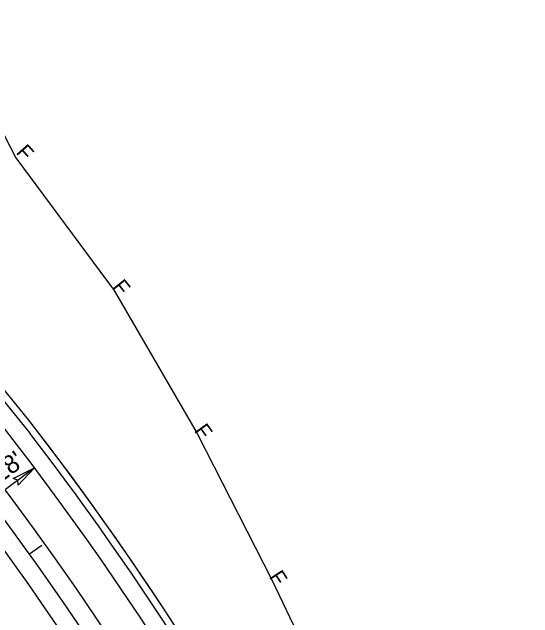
# Model space of a CAD drawing. Extents: x 1702862 to 1704514, y 793768 to 796215.
# Drawn here: x 1703795.7 to 1703965.8, y 794687 to 794884.7 of the extents above; entities that cross this region are included whole.
import ezdxf

# ---------------------------------------------------------------- set-up
doc = ezdxf.new("R2010")
doc.units = 0
for name, color, linetype in [('Prop Conc 2ft 6in Curb and Gutter', 7, 'Continuous'), ('Prop Conc Shoulder Berm Gutter', 7, 'Continuous'), ('Prop Dimension', 7, 'Continuous'), ('Prop Dimension Text', 7, 'Continuous'), ('Prop EOT', 7, 'Continuous'), ('Prop Guardrail', 7, 'Continuous'), ('Prop Horizontal Alignment', 7, 'Continuous'), ('Prop Horizontal Alignment Tick Small', 7, 'Continuous'), ('Prop Lane Lines', 7, 'Continuous'), ('Prop Paved Shoulder', 7, 'Continuous'), ('Prop SS Fill Line', 7, 'Continuous'), ('Prop SS Misc', 7, 'Continuous'), ('Prop Terminator CELL', 7, 'Continuous')]:
    doc.layers.add(name, color=color, linetype=linetype)

msp = doc.modelspace()

# ---------------------------------------------------------------- linework, layer by layer
at = {"layer": 'Prop Conc 2ft 6in Curb and Gutter'}
msp.add_arc((1702985.28, 794122.36), 970.46, 32.25438, 42.65517, dxfattribs=at)
at = {"layer": 'Prop Conc Shoulder Berm Gutter'}
for centre, radius, start, end in [((1703001.88, 794109.24), 1025.44, 38.5857, 43.82566), ((1702988.97, 794124.56), 1026.16, 26.22656, 37.4674)]:
    msp.add_arc(centre, radius, start, end, dxfattribs=at)
at = {"layer": 'Prop Dimension'}
msp.add_line((1703803.04, 794736.07), (1703788.65, 794725.26), dxfattribs=at)
at = {"layer": 'Prop EOT'}
for centre, radius, start, end in [((1702989.11, 794124.65), 1018, 14.75888, 42.70907), ((1702985.01, 794122.19), 972.78, 32.25419, 42.65174)]:
    msp.add_arc(centre, radius, start, end, dxfattribs=at)
at = {"layer": 'Prop Guardrail'}
for centre, radius, start, end in [((1703001.88, 794109.24), 1025.44, 38.5857, 43.82566), ((1702988.97, 794124.56), 1026.16, 25.61718, 37.4674)]:
    msp.add_arc(centre, radius, start, end, dxfattribs=at)
at = {"layer": 'Prop Horizontal Alignment'}
msp.add_arc((1702989.11, 794124.65), 1000, 351.25916, 42.70907, dxfattribs=at)
at = {"layer": 'Prop Horizontal Alignment Tick Small'}
msp.add_line((1703801.4, 794707.9), (1703805.46, 794710.81), dxfattribs=at)
at = {"layer": 'Prop Lane Lines'}
for radius, start in [(1006, 0.00687), (994, 359.40932), (980, 359.40932)]:
    msp.add_arc((1702989.11, 794124.65), radius, start, 42.70907, dxfattribs=at)
at = {"layer": 'Prop Paved Shoulder'}
for centre, radius, start, end in [((1703001.88, 794109.24), 1023.11, 38.5857, 43.82566), ((1702988.97, 794124.56), 1023.83, 26.22656, 37.4674)]:
    msp.add_arc(centre, radius, start, end, dxfattribs=at)
at = {"layer": 'Prop SS Fill Line'}
for p, q in [((1703772.29, 794884.75), (1703797.01, 794837.14)), ((1703797.01, 794837.14), (1703829.13, 794793.89)), ((1703829.13, 794793.89), (1703856.18, 794747.23)), ((1703856.18, 794747.23), (1703880.62, 794699.51)), ((1703880.62, 794699.51), (1703903.35, 794651.42))]:
    msp.add_line(p, q, dxfattribs=at)
at = {"layer": 'Prop Terminator CELL'}
msp.add_lwpolyline([(1703796.13, 794732.53), (1703803.04, 794736.07), (1703797.7, 794730.37), (1703797.67, 794732.04)], close=True, dxfattribs=at)

# ---------------------------------------------------------------- texts
at = {"layer": 'Prop Dimension Text'}
msp.add_text("18'", height=6, rotation=36.9141, dxfattribs=at).set_placement((1703791.81, 794730.85))
at = {"layer": 'Prop SS Misc'}
for rotation, p in [(311.4091, (1703796.8, 794838.84)), (308.5443, (1703828.25, 794795)), (305.6795, (1703855.04, 794748.15)), (302.8147, (1703879.52, 794700.49))]:
    msp.add_text('F', height=5, rotation=rotation, dxfattribs=at).set_placement(p)

doc.saveas('drawing.dxf')
